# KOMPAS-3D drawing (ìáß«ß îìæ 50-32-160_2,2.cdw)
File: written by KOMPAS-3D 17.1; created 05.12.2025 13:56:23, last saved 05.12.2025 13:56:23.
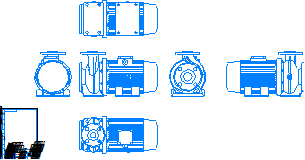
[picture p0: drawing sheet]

Sheet 1: A4, portrait

Title block, sheet 1: name: Насос МНС / 50-32-200_4.0; material: Сталь 10  ГОСТ 1050-88; mass: 81,27; sheets: 1; sheet format: A4

Views: Проекционный вид 2, Проекционный вид 3, Проекционный вид 4, Проекционный вид 5, Проекционный вид 6
Referenced files in \\adlc.lan\data\АДЛ_ПКД\3D-модели\ADL production\Насосы ГРАНПАМП\Насосы ГРАНПАМП серии МНС\KOMPAS 3D\: Насос МНС 50-32-160_2,2.m3d
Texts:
  Andrey
  АДЛ
Dimensions and other numbers on the sheet: 1:1; 1; 50-32-200_4.0; 81,27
